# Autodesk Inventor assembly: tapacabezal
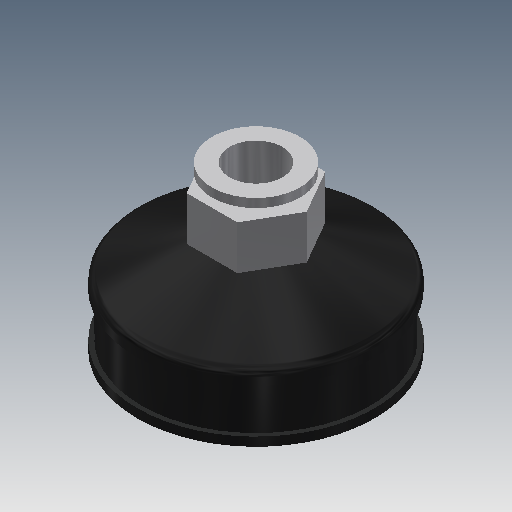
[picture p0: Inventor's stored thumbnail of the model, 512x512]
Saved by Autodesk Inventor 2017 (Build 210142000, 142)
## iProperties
Created: 2018-11
Part Number: tapacabezal
Document SubType Name: Assembly
Designer: JK
Author: JK
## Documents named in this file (3)
- C:\Users\JK\Documents\Inventor\BioExtruder\tapacabezal.iam
- C:\Users\JK\Documents\Inventor\BioExtruder\Conector6mm.ipt
- C:\Users\JK\Documents\Inventor\BioExtruder\Syringe_60ml_rubber.ipt
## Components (2 placed, 2 different names)
1. Conector6mm:1 — Mate:1, Flush:1
2. Syringe_60ml_rubber:1 — Mate:1, Flush:1
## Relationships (2: Mate 1, Flush 1)
- Mate:1: Conector6mm:1 ↔ Syringe_60ml_rubber:1
- Flush:1: Conector6mm:1 ↔ Syringe_60ml_rubber:1
